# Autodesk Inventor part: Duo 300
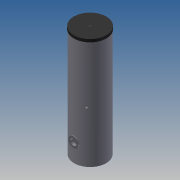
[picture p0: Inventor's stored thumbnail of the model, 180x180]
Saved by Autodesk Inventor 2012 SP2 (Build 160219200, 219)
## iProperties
Created: 2014-05
Part Number: Duo 300
Material: Default
Document SubType Name: Modeling
Designer: michel
Density: 1 g/cm^3
Author: michel
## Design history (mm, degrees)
sketch "Sketch1"
  geometry: C1 r 280 at (0, 0); 1 further point
  constraints: 1 centre point, 1 coincident
  dimensions: "d0" = 560 diameter of C1
extrude "Extrusion1" new body sketch "Sketch1" distance "d1" = 1950; taper "d2" = 0 deg
sketch "Sketch2"
  geometry: L1 (-280, 1950)-(280, 1950) reference; L2 (280, 0)-(280, 1950) reference; L3 (280, 1950)-(280, 1900); L4 (285, 1900)-(285, 1950); L5 (285, 1950)-(280, 1950); L6 (0, -290)-(0, 1740) reference; L7 (285, 1900)-(280, 1900); 1 further point
  constraints: 8 end point, 1 parallel
revolve "Revolution1" sketch "Sketch2" stored, may be unused: angle "d6" = 90 deg
workplane "Work Plane1"
workplane "Work Plane2"
workplane "Work Plane3"
workplane "Work Plane4"
workplane "Work Plane5"
workplane "Work Plane6"
sketch "Sketch3"
  geometry: L1 (404, 1785)-(-394, 1785) reference; L2 (404, 910)-(-394, 910) reference; L3 (404, 1035)-(-394, 1035) reference; L4 (404, 245)-(-394, 245) reference; L5 (404, 65)-(-394, 65) reference; L6 (280, 0)-(280, 1900) reference; L7 (290, 1785)-(240, 1785); L8 (240, 1785)-(240, 1801.625); L9 (240, 1801.625)-(290, 1801.625); L10 (290, 1801.625)-(290, 1785); L11 (290, 65)-(240, 65); L12 (240, 65)-(240, 81.625); L13 (240, 81.625)-(290, 81.625); L14 (290, 81.625)-(290, 65); L15 (280, 910)-(240, 910); L16 (240, 910)-(240, 920.475); L17 (240, 920.475)-(280, 920.475); L18 (280, 920.475)-(280, 910); L19 (280, 1035)-(240, 1035); L20 (240, 1035)-(240, 1051.625); L21 (240, 1051.625)-(280, 1051.625); L22 (280, 1051.625)-(280, 1035); L23 (240, 261.625)-(280, 261.625); L24 (280, 261.625)-(280, 245); L25 (280, 245)-(240, 245); L26 (240, 245)-(240, 261.625); 1 further point
  constraints: 40 end point, 8 parallel, 4 point on line, 3 horizontal, 3 perpendicular
  dimensions: "d13" = 50 distance of L8.end L9.end; "d14" = 16.625 distance of L7.end L8.end; "d15" = 50 distance of L12.end L13.end; "d16" = 16.625 distance of L11.end L12.end; "d17" = 40 distance of L16.end L17.end; "d18" = 10.475 distance of L15.end L16.end; "d19" = 40 distance of L20.end L21.end; "d20" = 16.625 distance of L19.end L20.end; "d21" = 40 distance of L23.start L23.end; "d22" = 16.625 distance of L25.end L23.start
revolve "Revolution2" stored, may be unused: angle "d23" = 90 deg
revolve "Revolution3" stored, may be unused: angle "d24" = 90 deg
revolve "Revolution4" stored, may be unused: angle "d25" = 90 deg
revolve "Revolution5" stored, may be unused: angle "d26" = 90 deg
revolve "Revolution6" stored, may be unused: angle "d27" = 90 deg
revolve "Revolution7" stored, may be unused: angle "d28" = 90 deg
revolve "Revolution8" stored, may be unused: angle "d29" = 90 deg
sketch "Sketch4"
  geometry: C1 r 16.625 at (0, 0) reference; C2 r 15.375 at (0, 0); 1 further point
  constraints: 1 centre point, 1 coincident
  dimensions: "d30" = 30.75 diameter of C2
extrude "Extrusion2" cut sketch "Sketch4" distance "d31" = 40; taper "d32" = 0 deg
sketch "Sketch5"
  geometry: C1 r 16.625 at (0, 0) reference; C2 r 15.375 at (0, 0); 1 further point
  constraints: 1 centre point, 1 coincident
  dimensions: "d33" = 30.75 diameter of C2
extrude "Extrusion3" cut sketch "Sketch5" distance "d34" = 40; taper "d35" = 0 deg
workplane "Work Plane7"
sketch "Sketch6"
  geometry: C1 r 9.5 at (0, 0); C2 r 16.625 at (0, 125) reference; C3 r 16.625 at (0, -665) reference; C4 r 15.375 at (0, 125); C5 r 15.375 at (0, -665); 7 further points
  constraints: 6 vertical alignment, 3 centre point, 2 coincident
  dimensions: "d36" = 19 diameter of C1; "d37" = 30.75 diameter of C4; "d38" = 30.75 diameter of C5
  node "Projected Loop1"
  node "Projected Loop2"
extrude "Extrusion4" join sketch "Sketch6" distance "d39" = 40; taper "d40" = 0 deg
extrude "Extrusion5" join sketch "Sketch6" distance "d41" = 40; taper "d42" = 0 deg
extrude "Extrusion6" join sketch "Sketch6" distance "d43" = 40; taper "d44" = 0 deg
workplane "Work Plane8"
workplane "Work Plane9"
sketch "Sketch7"
  geometry: L1 (394.5, 327)-(-407, 327) reference; L2 (-280, 0)-(-280, 1900) reference; L3 (-280, 327)-(-292.5, 327); L4 (-292.5, 327)-(-292.5, 417); L5 (-292.5, 417)-(-280, 417); L6 (-280, 417)-(-280, 327); 1 further point
  constraints: 8 end point, 2 parallel, 2 point on line, 1 horizontal, 1 perpendicular
  dimensions: "d47" = 12.5 distance of L4.end L5.end; "d48" = 90 distance of L3.end L4.end
revolve "Revolution9" sketch "Sketch7" stored, may be unused: angle "d49" = 90 deg
sketch "Sketch8"
  geometry: C1 r 62.5 at (0, 0); A1 r 90 centre (0, 0) between (0, -90) and (0, 90) reference; 1 further point
  constraints: 1 centre point, 1 coincident
  dimensions: "d50" = 125 diameter of C1
extrude "Extrusion7" join sketch "Sketch8" stored distance "d51" = 10; taper "d52" = 0 deg
sketch "Sketch9"
  geometry: C1 r 90 at (0, 0) reference; C2 r 55 at (0, 0); 1 further point
  constraints: 1 centre point, 1 coincident
  dimensions: "d53" = 110 diameter of C2
extrude "Extrusion8" cut sketch "Sketch9" distance "d54" = 50; taper "d55" = 0 deg
sketch "Sketch10"
  geometry: C1 r 285 at (0, 0) reference; C2 r 20.955 at (0, 0); C3 r 19.625 at (0, 0)
  constraints: 2 centre point, 2 coincident
  dimensions: "d56" = 41.91 diameter of C2; "d59" = 39.25 diameter of C3
extrude "Extrusion9" cut sketch "Sketch10" distance "d57" = 50; taper "d58" = 0 deg
extrude "Extrusion10" join sketch "Sketch10" distance "d60" = 50; taper "d61" = 0 deg
workplane "Work Plane10"
sketch "Sketch11"
  geometry: L1 (910, -545.95)-(910, 545.95) reference; L2 (0, 280)-(1900, 280) reference; L3 (910, 280)-(933.9, 280); L4 (933.9, 280)-(933.9, 240); L5 (933.9, 240)-(910, 240); L6 (910, 240)-(910, 280); L7 (887.375, 240)-(887.375, 280); L8 (887.375, 240)-(884.825, 240); L9 (884.825, 240)-(884.825, 280); L10 (887.375, 280)-(884.825, 280); 1 further point
  constraints: 16 end point, 4 perpendicular, 4 point on line, 2 parallel, 1 horizontal
  dimensions: "d63" = 23.9 distance of L4.end L5.end; "d64" = 40 distance of L3.end L4.end; "d67" = 22.625 distance of L5.end L7.start; "d68" = 2.55 distance of L7.start L8.end
revolve "Revolution10" stored, may be unused: angle "d65" = 90 deg
revolve "Revolution11" stored, may be unused: angle "d69" = 90 deg
body "Solid1"
other parameters: "d8" = -65, "d9" = -245, "d12" = 0, "d45" = -327, "d46" = 0, "d62" = 35 deg, "d76" = -1785, "d77" = -1035
